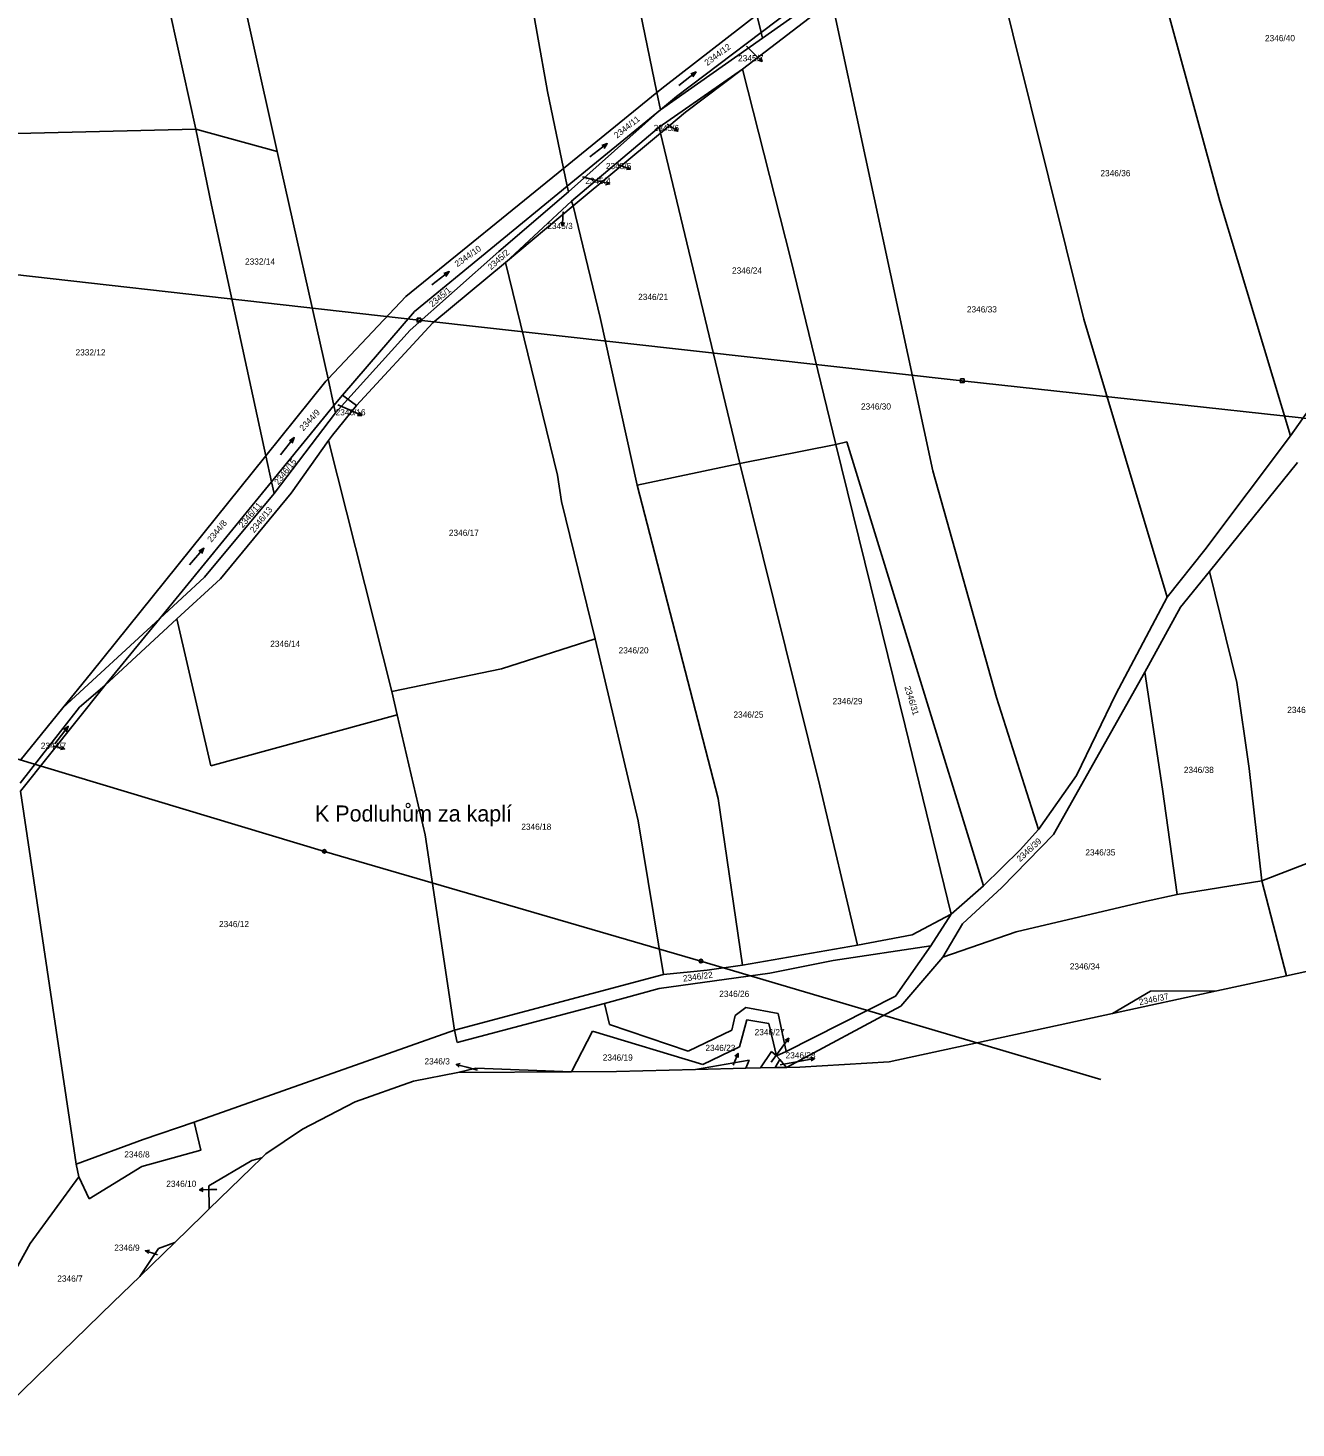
# Model space of a CAD drawing. Extents: x -785744 to -782822, y -1067550 to -1063910.
# Drawn here: x -784252.2 to -783904.8, y -1067104.2 to -1066720.6 of the extents above; entities that cross this region are included whole.
import ezdxf

# ---------------------------------------------------------------- set-up
doc = ezdxf.new("R2010")
doc.units = 0
for name, color, linetype in [('Hranice obce', 7, 'Continuous'), ('Hranice parcel', 7, 'Continuous'), ('Parcelní čísla', 7, 'Continuous'), ('Pop_ČP_popisy', 7, 'Continuous'), ('Poz_předměty', 7, 'Continuous'), ('Značky kultur', 7, 'Continuous')]:
    doc.layers.add(name, color=color, linetype=linetype)

msp = doc.modelspace()

# ---------------------------------------------------------------- linework, layer by layer
at = {"layer": 'Hranice obce'}
msp.add_lwpolyline([(-783886.43, -1066975.8), (-783907.33, -1066980.32), (-783926.48, -1066984.47), (-783955.08, -1066990.66), (-784016.28, -1067003.9), (-784040.7, -1067005.32), (-784044.43, -1067005.41), (-784047.51, -1067005.48), (-784051.51, -1067005.57), (-784055.55, -1067005.67), (-784069.33, -1067005.99), (-784090.94, -1067006.5), (-784103.34, -1067006.59), (-784134.44, -1067006.81), (-784146.59, -1067009.18), (-784162.59, -1067014.83), (-784177.06, -1067022.33), (-784187.03, -1067029.09), (-784188.18, -1067030.21), (-784191.03, -1067032.97), (-784202.56, -1067044.18), (-784204.29, -1067045.86), (-784212.05, -1067053.39), (-784221.6, -1067062.68), (-784228.88, -1067069.75), (-784264.38, -1067104.23)], dxfattribs=at)
at = {"layer": 'Hranice parcel'}
for points in [[(-784204.18, -1066663.69), (-784183.94, -1066754.46)], [(-783992.04, -1066683.23), (-783962.93, -1066800.38)], [(-784088.45, -1066696.92), (-784079.9, -1066738.26)], [(-784115.59, -1066706.11), (-784109.93, -1066738.01)], [(-784214.9, -1066708.95), (-784206.23, -1066748.36)], [(-784051.37, -1066721.83), (-784033.39, -1066708.18)], [(-784050.99, -1066723.37), (-784032.82, -1066710.52)], [(-784056.45, -1066731.84), (-784031.93, -1066713.19)], [(-784031.93, -1066713.19), (-784004.31, -1066841.92)], [(-783940.87, -1066712.28), (-783925.65, -1066768.03)], [(-784077.74, -1066736.51), (-784052.55, -1066716.99)], [(-784052.55, -1066716.99), (-784051.37, -1066721.83)], [(-784074.51, -1066739.4), (-784051.37, -1066721.83)], [(-784051.37, -1066721.83), (-784050.99, -1066723.37)], [(-784078.92, -1066743.01), (-784050.99, -1066723.37)], [(-784079.33, -1066747.74), (-784056.45, -1066731.84)], [(-784072.04, -1066743.7), (-784056.45, -1066731.84)], [(-784056.45, -1066731.84), (-784043.21, -1066783.99)], [(-784079.9, -1066738.26), (-784077.74, -1066736.51)], [(-784109.93, -1066738.01), (-784105.51, -1066759.06)], [(-784105.51, -1066759.06), (-784079.9, -1066738.26)], [(-784079.9, -1066738.26), (-784078.92, -1066743.01)], [(-784078.92, -1066743.01), (-784074.51, -1066739.4)], [(-784104.48, -1066763.97), (-784078.92, -1066743.01)], [(-784104.15, -1066765.51), (-784078.92, -1066743.01)], [(-784078.92, -1066749.43), (-784072.04, -1066743.7)], [(-784293.05, -1066750.45), (-784206.23, -1066748.36)], [(-784206.23, -1066748.36), (-784183.94, -1066754.46)], [(-784206.23, -1066748.36), (-784201.95, -1066769.19)], [(-784103.29, -1066768.03), (-784079.33, -1066747.74)], [(-784079.33, -1066747.74), (-784078.92, -1066749.43)], [(-784102.81, -1066769.33), (-784078.92, -1066749.43)], [(-784078.92, -1066749.43), (-784057.16, -1066839.95)], [(-784183.94, -1066754.46), (-784170.03, -1066816.7)], [(-784148.75, -1066794.2), (-784105.51, -1066759.06)], [(-784105.51, -1066759.06), (-784104.48, -1066763.97)], [(-784146.3, -1066798.26), (-784104.48, -1066763.97)], [(-784104.48, -1066763.97), (-784104.15, -1066765.51)], [(-784123.22, -1066781.8), (-784104.15, -1066765.51)], [(-784121.39, -1066784.81), (-784103.29, -1066768.03)], [(-784103.29, -1066768.03), (-784102.81, -1066769.33)], [(-783925.65, -1066768.03), (-783906.28, -1066832.31)], [(-784201.95, -1066769.19), (-784187.08, -1066837.8)], [(-784121.39, -1066784.81), (-784102.81, -1066769.33)], [(-784102.81, -1066769.33), (-784095.47, -1066799.89)], [(-784147.53, -1066803.39), (-784123.22, -1066781.8)], [(-783906.28, -1066832.31), (-783869.57, -1066780.28)], [(-784141.34, -1066801.43), (-784121.39, -1066784.81)], [(-784121.39, -1066784.81), (-784107.19, -1066843.12)], [(-784043.21, -1066783.99), (-784030.84, -1066834.69)], [(-784170.03, -1066816.7), (-784148.75, -1066794.2)], [(-784166.09, -1066821.18), (-784146.3, -1066798.26)], [(-784162.26, -1066824), (-784141.34, -1066801.43)], [(-784095.47, -1066799.89), (-784085.3, -1066845.89)], [(-783962.93, -1066800.38), (-783940.05, -1066876.6)], [(-784164.59, -1066822.29), (-784147.53, -1066803.39)], [(-784187.08, -1066837.8), (-784170.62, -1066817.33)], [(-784170.62, -1066817.33), (-784170.03, -1066816.7)], [(-784170.03, -1066816.7), (-784168.4, -1066824)], [(-784168.4, -1066824), (-784166.09, -1066821.18)], [(-784166.09, -1066821.18), (-784164.59, -1066822.29)], [(-784185.53, -1066844.95), (-784168.4, -1066824)], [(-784168.79, -1066832.13), (-784162.26, -1066824)], [(-784168.4, -1066824), (-784167.95, -1066826.01)], [(-784167.95, -1066826.01), (-784164.59, -1066822.29)], [(-784164.59, -1066822.29), (-784162.26, -1066824)], [(-784184.83, -1066848.19), (-784167.95, -1066826.01)], [(-784169.88, -1066833.63), (-784168.79, -1066832.13)], [(-783929.74, -1066863.56), (-783906.28, -1066832.31)], [(-784180.1, -1066848.06), (-784169.88, -1066833.63)], [(-784169.88, -1066833.63), (-784152.56, -1066902.43)], [(-784057.16, -1066839.95), (-784030.84, -1066834.69)], [(-784030.84, -1066834.69), (-784027.89, -1066834.04)], [(-784030.84, -1066834.69), (-784011.91, -1066911.86)], [(-784027.89, -1066834.04), (-783990.41, -1066955.7)], [(-784235.14, -1066897.55), (-784187.08, -1066837.8)], [(-784187.08, -1066837.8), (-784185.53, -1066844.95)], [(-784085.3, -1066845.89), (-784057.16, -1066839.95)], [(-784057.16, -1066839.95), (-784035.26, -1066928.28)], [(-783928.5, -1066869.5), (-783904.4, -1066839.63)], [(-784107.19, -1066843.12), (-784106.03, -1066850.37)], [(-784004.31, -1066841.92), (-783986.81, -1066904.1)], [(-784216.15, -1066882.38), (-784185.53, -1066844.95)], [(-784203.89, -1066871.08), (-784184.83, -1066848.19)], [(-784199.5, -1066871.5), (-784180.1, -1066848.06)], [(-784185.53, -1066844.95), (-784184.83, -1066848.19)], [(-784085.3, -1066845.89), (-784063.16, -1066931.74)], [(-784106.03, -1066850.37), (-784096.78, -1066887.99)], [(-783940.05, -1066876.6), (-783929.74, -1066863.56)], [(-784216.15, -1066882.38), (-784203.89, -1066871.08)], [(-784211.45, -1066882.54), (-784199.5, -1066871.5)], [(-783936.42, -1066879.33), (-783928.5, -1066869.5)], [(-783928.5, -1066869.5), (-783921.01, -1066899.95)], [(-783954.15, -1066903.15), (-783940.05, -1066876.6)], [(-783946.2, -1066897.15), (-783936.42, -1066879.33)], [(-784242.71, -1066906.87), (-784216.15, -1066882.38)], [(-784231.22, -1066900.81), (-784216.15, -1066882.38)], [(-784231.22, -1066900.81), (-784211.45, -1066882.54)], [(-784211.45, -1066882.54), (-784202.11, -1066922.81)], [(-784122.52, -1066896.22), (-784096.78, -1066887.99)], [(-784096.78, -1066887.99), (-784085.01, -1066937.87)], [(-784242.71, -1066906.87), (-784235.14, -1066897.55)], [(-784152.56, -1066902.43), (-784122.52, -1066896.22)], [(-783971.18, -1066941.61), (-783946.2, -1066897.15)], [(-783946.2, -1066897.15), (-783941.34, -1066929.13)], [(-784254.29, -1066929.76), (-784231.22, -1066900.81)], [(-784238.09, -1066906.74), (-784231.22, -1066900.81)], [(-783921.01, -1066899.95), (-783917.6, -1066923.49)], [(-784152.56, -1066902.43), (-784151.07, -1066908.84)], [(-783986.81, -1066904.1), (-783975.33, -1066940.24)], [(-783964.89, -1066925.41), (-783954.15, -1066903.15)], [(-784254.42, -1066927.56), (-784238.09, -1066906.74)], [(-784254.41, -1066921.28), (-784242.71, -1066906.87)], [(-784202.11, -1066922.81), (-784151.07, -1066908.84)], [(-784151.07, -1066908.84), (-784143.44, -1066941.68)], [(-784011.91, -1066911.86), (-783999.23, -1066963.41)], [(-783975.33, -1066940.24), (-783964.89, -1066925.41)], [(-783917.6, -1066923.49), (-783914.1, -1066954.26)], [(-784035.26, -1066928.28), (-784024.96, -1066971.89)], [(-783941.34, -1066929.13), (-783937.29, -1066958.07)], [(-784254.29, -1066929.76), (-784239.02, -1067031.89)], [(-784063.16, -1066931.74), (-784056.41, -1066977.36)], [(-784085.01, -1066937.87), (-784078.08, -1066979.95)], [(-783980.32, -1066945.77), (-783975.33, -1066940.24)], [(-784143.44, -1066941.68), (-784135.37, -1066995.23)], [(-783985.41, -1066956.1), (-783971.18, -1066941.61)], [(-783990.41, -1066955.7), (-783980.32, -1066945.77)], [(-783914.1, -1066954.26), (-783897.3, -1066947.84)], [(-783999.23, -1066963.41), (-783990.41, -1066955.7)], [(-783996.18, -1066966.09), (-783985.41, -1066956.1)], [(-783937.29, -1066958.07), (-783914.1, -1066954.26)], [(-783914.1, -1066954.26), (-783907.33, -1066980.32)], [(-783946.54, -1066960.05), (-783937.29, -1066958.07)], [(-784009.99, -1066969.07), (-783999.23, -1066963.41)], [(-784004.87, -1066972.09), (-783999.23, -1066963.41)], [(-783981.49, -1066968.31), (-783946.54, -1066960.05)], [(-784001.59, -1066975.25), (-783996.18, -1066966.09)], [(-784024.96, -1066971.89), (-784009.99, -1066969.07)], [(-784001.59, -1066975.25), (-783981.49, -1066968.31)], [(-784056.41, -1066977.36), (-784024.96, -1066971.89)], [(-784031.59, -1066976.09), (-784004.87, -1066972.09)], [(-784014.49, -1066985.89), (-784004.87, -1066972.09)], [(-784013.06, -1066988.67), (-784001.59, -1066975.25)], [(-784078.08, -1066979.95), (-784066.15, -1066978.73)], [(-784066.15, -1066978.73), (-784056.41, -1066977.36)], [(-784048.96, -1066979.59), (-784031.59, -1066976.09)], [(-784135.37, -1066995.23), (-784078.08, -1066979.95)], [(-784079.33, -1066983.78), (-784048.96, -1066979.59)], [(-784094.24, -1066987.95), (-784079.33, -1066983.78)], [(-784044.5, -1067001.08), (-784014.49, -1066985.89)], [(-783955.08, -1066990.66), (-783944.62, -1066984.53)], [(-783944.62, -1066984.53), (-783926.48, -1066984.47)], [(-784134.61, -1066998.61), (-784094.24, -1066987.95)], [(-784094.24, -1066987.95), (-784092.94, -1066993.65)], [(-784058.49, -1066991.2), (-784055.5, -1066988.96)], [(-784055.5, -1066988.96), (-784046.69, -1066990.68)], [(-784044.43, -1067005.41), (-784013.06, -1066988.67)], [(-784092.94, -1066993.65), (-784071.33, -1067000.97)], [(-784059.35, -1066995.21), (-784058.49, -1066991.2)], [(-784057.27, -1066999.74), (-784055.3, -1066992.34)], [(-784055.3, -1066992.34), (-784049.23, -1066993.4)], [(-784049.23, -1066993.4), (-784047.17, -1067002.22)], [(-784046.69, -1066990.68), (-784044.5, -1067001.08)], [(-784206.72, -1067020.46), (-784135.37, -1066995.23)], [(-784135.37, -1066995.23), (-784134.61, -1066998.61)], [(-784103.34, -1067006.59), (-784097.52, -1066995.46)], [(-784097.52, -1066995.46), (-784067.3, -1067004.62)], [(-784071.33, -1067000.97), (-784059.35, -1066995.21)], [(-784067.3, -1067004.62), (-784057.27, -1066999.74)], [(-784051.51, -1067005.57), (-784048.53, -1067001.05)], [(-784048.53, -1067001.05), (-784047.17, -1067002.22)], [(-784047.17, -1067002.22), (-784044.5, -1067001.08)], [(-784134.44, -1067006.81), (-784129.53, -1067005.59)], [(-784129.53, -1067005.59), (-784103.34, -1067006.59)], [(-784069.33, -1067005.99), (-784054.63, -1067003.41)], [(-784055.55, -1067005.67), (-784054.63, -1067003.41)], [(-784047.51, -1067005.48), (-784046.23, -1067003.23)], [(-784047.17, -1067002.22), (-784046.23, -1067003.23)], [(-784046.23, -1067003.23), (-784044.43, -1067005.41)], [(-784220.67, -1067025.15), (-784206.72, -1067020.46)], [(-784206.72, -1067020.46), (-784204.91, -1067028.13)], [(-784239.02, -1067031.89), (-784220.67, -1067025.15)], [(-784221.02, -1067032.54), (-784204.91, -1067028.13)], [(-784239.02, -1067031.89), (-784238.31, -1067035.39)], [(-784235.49, -1067041.47), (-784221.02, -1067032.54)], [(-784202.68, -1067037.88), (-784190.95, -1067030.89)], [(-784190.95, -1067030.89), (-784188.18, -1067030.21)], [(-784251.67, -1067053.63), (-784238.31, -1067035.39)], [(-784238.31, -1067035.39), (-784235.49, -1067041.47)], [(-784202.68, -1067037.88), (-784202.56, -1067044.18)], [(-784260.04, -1067068.7), (-784251.67, -1067053.63)], [(-784221.6, -1067062.68), (-784216.5, -1067055.07)], [(-784216.5, -1067055.07), (-784212.05, -1067053.39)]]:
    msp.add_lwpolyline(points, dxfattribs=at)
at = {"layer": 'Pop_ČP_popisy'}
for p, q in [((-784053.23, -1066727.64), (-784051.09, -1066729.74)), ((-784076.68, -1066747.23), (-784074.15, -1066748.84)), ((-784089.99, -1066758.28), (-784087.16, -1066759.27)), ((-784095.78, -1066762.56), (-784092.88, -1066763.34)), ((-784105.64, -1066771.86), (-784105.74, -1066774.86)), ((-784163.54, -1066825.53), (-784160.8, -1066826.75)), ((-784245.14, -1066917.35), (-784242.24, -1066918.13)), ((-784045.56, -1066999.85), (-784043.79, -1066997.43)), ((-784058.82, -1067004.37), (-784057.68, -1067001.59)), ((-784131.99, -1067005.39), (-784134.89, -1067004.61)), ((-784039.65, -1067003.49), (-784036.7, -1067002.95)), ((-784202.23, -1067038.92), (-784205.23, -1067038.98)), ((-784217.2, -1067056.6), (-784220.05, -1067055.66))]:
    msp.add_line(p, q, dxfattribs=at)
for points in [[(-784055.33, -1066725.59), (-784053.23, -1066727.64)], [(-784051.45, -1066728.68), (-784051.09, -1066729.74), (-784052.15, -1066729.4)], [(-784077.1, -1066746.97), (-784076.68, -1066747.23)], [(-784074.72, -1066747.88), (-784074.15, -1066748.84), (-784075.26, -1066748.72)], [(-784090.48, -1066758.11), (-784089.99, -1066758.28)], [(-784087.94, -1066758.47), (-784087.16, -1066759.27), (-784088.27, -1066759.41)], [(-784100.31, -1066761.35), (-784095.78, -1066762.56)], [(-784093.72, -1066762.59), (-784092.88, -1066763.34), (-784093.98, -1066763.56)], [(-784105.61, -1066770.96), (-784105.64, -1066771.86)], [(-784105.21, -1066773.88), (-784105.74, -1066774.86), (-784106.21, -1066773.84)], [(-784167.31, -1066823.85), (-784163.54, -1066825.53)], [(-784161.51, -1066825.89), (-784160.8, -1066826.75), (-784161.92, -1066826.8)], [(-784245.31, -1066917.3), (-784245.14, -1066917.35)], [(-784243.08, -1066917.39), (-784242.24, -1066918.13), (-784243.34, -1066918.35)], [(-784044.78, -1066997.94), (-784043.79, -1066997.43), (-784043.98, -1066998.53)], [(-784058.52, -1067002.33), (-784057.68, -1067001.59), (-784057.6, -1067002.71)], [(-784048.56, -1067003.95), (-784045.56, -1066999.85)], [(-784134.05, -1067005.35), (-784134.89, -1067004.61), (-784133.79, -1067004.39)], [(-784129.05, -1067006.19), (-784131.99, -1067005.39)], [(-784059.01, -1067004.83), (-784058.82, -1067004.37)], [(-784046.16, -1067004.69), (-784039.65, -1067003.49)], [(-784037.77, -1067002.64), (-784036.7, -1067002.95), (-784037.59, -1067003.62)], [(-784204.22, -1067039.46), (-784205.23, -1067038.98), (-784204.24, -1067038.46)], [(-784200.5, -1067038.89), (-784202.23, -1067038.92)], [(-784219.26, -1067056.45), (-784220.05, -1067055.66), (-784218.94, -1067055.5)], [(-784216.77, -1067056.74), (-784217.2, -1067056.6)]]:
    msp.add_lwpolyline(points, dxfattribs=at)
at = {"layer": 'Poz_předměty'}
for points in [[(-784298.77, -1066783.28), (-784145.12, -1066800.64)], [(-784145.12, -1066800.64), (-783996.24, -1066817.26)], [(-783996.24, -1066817.26), (-783847.28, -1066833.54)], [(-784271.45, -1066916.06), (-784171.04, -1066946.21)], [(-784171.04, -1066946.21), (-784067.83, -1066976.3)], [(-784067.83, -1066976.3), (-783958.28, -1067008.73)]]:
    msp.add_lwpolyline(points, dxfattribs=at)
for points in [[(-784145.62, -1066800.14), (-784144.62, -1066800.14), (-784144.62, -1066801.14), (-784145.62, -1066801.14)], [(-783996.74, -1066816.76), (-783995.74, -1066816.76), (-783995.74, -1066817.76), (-783996.74, -1066817.76)]]:
    msp.add_lwpolyline(points, close=True, dxfattribs=at)
for centre in [(-784171.04, -1066946.21), (-784067.83, -1066976.3)]:
    msp.add_circle(centre, 0.5, dxfattribs=at)
at = {"layer": 'Značky kultur'}
for points in [[(-784073.87, -1066736.37), (-784069.17, -1066732.65), (-784070.65, -1066733.19)], [(-784069.17, -1066732.65), (-784070.03, -1066733.97)], [(-784098.29, -1066755.9), (-784093.49, -1066752.28), (-784094.99, -1066752.79)], [(-784093.49, -1066752.28), (-784094.39, -1066753.59)], [(-784141.59, -1066791), (-784136.83, -1066787.36), (-784138.32, -1066787.87)], [(-784136.83, -1066787.36), (-784137.71, -1066788.67)], [(-784183.04, -1066837.53), (-784179.28, -1066832.85), (-784180.61, -1066833.71)], [(-784179.28, -1066832.85), (-784179.83, -1066834.33)], [(-784207.97, -1066867.69), (-784204.05, -1066863.15), (-784205.41, -1066863.96)], [(-784204.05, -1066863.15), (-784204.65, -1066864.61)], [(-784244.91, -1066916.73), (-784241.23, -1066911.99), (-784242.54, -1066912.87)], [(-784241.23, -1066911.99), (-784241.75, -1066913.48)]]:
    msp.add_lwpolyline(points, dxfattribs=at)

# ---------------------------------------------------------------- texts
at = {"layer": 'Parcelní čísla'}
for s, rotation, p in [('2344/12', 36.7455, (-784066.08, -1066731.04)), ('2344/11', 38.2222, (-784090.83, -1066750.93)), ('2344/10', 35.2256, (-784134.59, -1066786.16)), ('2345/2', 41.6869, (-784125.35, -1066787)), ('2345/1', 40.1704, (-784141.45, -1066797.18)), ('2344/9', 47.3176, (-784176.79, -1066831.15)), ('2346/15', 51.8733, (-784183.61, -1066845.92)), ('2346/11', 49.1792, (-784193.41, -1066857.71)), ('2346/13', 51.4347, (-784190.26, -1066859.06)), ('2344/8', 50.6911, (-784202, -1066861.68)), ('2346/31', 287.107, (-784012.09, -1066901.19)), ('2346/39', 42.5639, (-783980.4, -1066949.2)), ('2346/22', 7.7501, (-784072.66, -1066981.93)), ('2346/37', 11.8159, (-783947.59, -1066988.39))]:
    msp.add_text(s, height=1.7, rotation=rotation, dxfattribs=at).set_placement(p)
for s, height, p in [('2345/7', 0.1, (-784055.33, -1066725.59)), ('2346/40', 1.7, (-783913.27, -1066724.22)), ('2345/6', 0.1, (-784077.1, -1066746.97)), ('2345/5', 0.1, (-784090.48, -1066758.11)), ('2346/36', 1.7, (-783958.36, -1066761.23)), ('2345/4', 0.1, (-784100.31, -1066761.35)), ('2345/3', 0.1, (-784105.61, -1066770.96)), ('2332/14', 1.7, (-784192.77, -1066785.45)), ('2346/24', 1.7, (-784059.32, -1066787.89)), ('2346/21', 1.7, (-784085.05, -1066795.14)), ('2346/33', 1.7, (-783994.96, -1066798.54)), ('2332/12', 1.7, (-784239.22, -1066810.33)), ('2346/16', 0.1, (-784167.31, -1066823.85)), ('2346/30', 1.7, (-784023.98, -1066825.15)), ('2346/17', 1.7, (-784136.91, -1066859.76)), ('2346/14', 1.7, (-784185.87, -1066890.19)), ('2346/20', 1.7, (-784090.4, -1066891.98)), ('2346/29', 1.7, (-784031.77, -1066905.89)), ('2346/25', 1.7, (-784058.93, -1066909.59)), ('2346/41', 1.7, (-783907.17, -1066908.3)), ('2344/7', 0.1, (-784245.31, -1066917.3)), ('2346/38', 1.7, (-783935.51, -1066924.74)), ('2346/18', 1.7, (-784117.06, -1066940.31)), ('2346/35', 1.7, (-783962.49, -1066947.34)), ('2346/12', 1.7, (-784199.9, -1066966.98)), ('2346/34', 1.7, (-783966.76, -1066978.59)), ('2346/26', 1.7, (-784062.82, -1066986.11)), ('2346/19', 1.7, (-784094.74, -1067003.56)), ('2346/23', 0.1, (-784059.01, -1067004.83)), ('2346/27', 0.1, (-784048.56, -1067003.95)), ('2346/28', 0.1, (-784046.16, -1067004.69)), ('2346/3', 0.1, (-784129.05, -1067006.19)), ('2346/8', 1.7, (-784225.86, -1067030.1)), ('2346/10', 0.1, (-784200.5, -1067038.89)), ('2346/9', 0.1, (-784216.77, -1067056.74)), ('2346/7', 1.7, (-784244.22, -1067064.14))]:
    msp.add_text(s, height=height, dxfattribs=at).set_placement(p)
at = {"layer": 'Pop_ČP_popisy'}
for s, height, p in [('2345/7', 1.7, (-784057.66, -1066729.74)), ('2345/6', 1.7, (-784080.79, -1066748.84)), ('2345/5', 1.7, (-784093.88, -1066759.27)), ('2345/4', 1.7, (-784099.52, -1066763.34)), ('2345/3', 1.7, (-784109.93, -1066775.69)), ('2346/16', 1.7, (-784167.96, -1066826.75)), ('2344/7', 1.7, (-784248.73, -1066918.13)), ('K Podluhům za kaplí', 4.4, (-784173.6, -1066938.05)), ('2346/27', 1.7, (-784053.12, -1066996.59)), ('2346/23', 1.7, (-784066.61, -1067000.93)), ('2346/28', 1.7, (-784044.64, -1067002.95)), ('2346/3', 1.7, (-784143.6, -1067004.61)), ('2346/10', 1.7, (-784214.35, -1067038.15)), ('2346/9', 1.7, (-784228.61, -1067055.66))]:
    msp.add_text(s, height=height, dxfattribs=at).set_placement(p)

doc.saveas('drawing.dxf')
